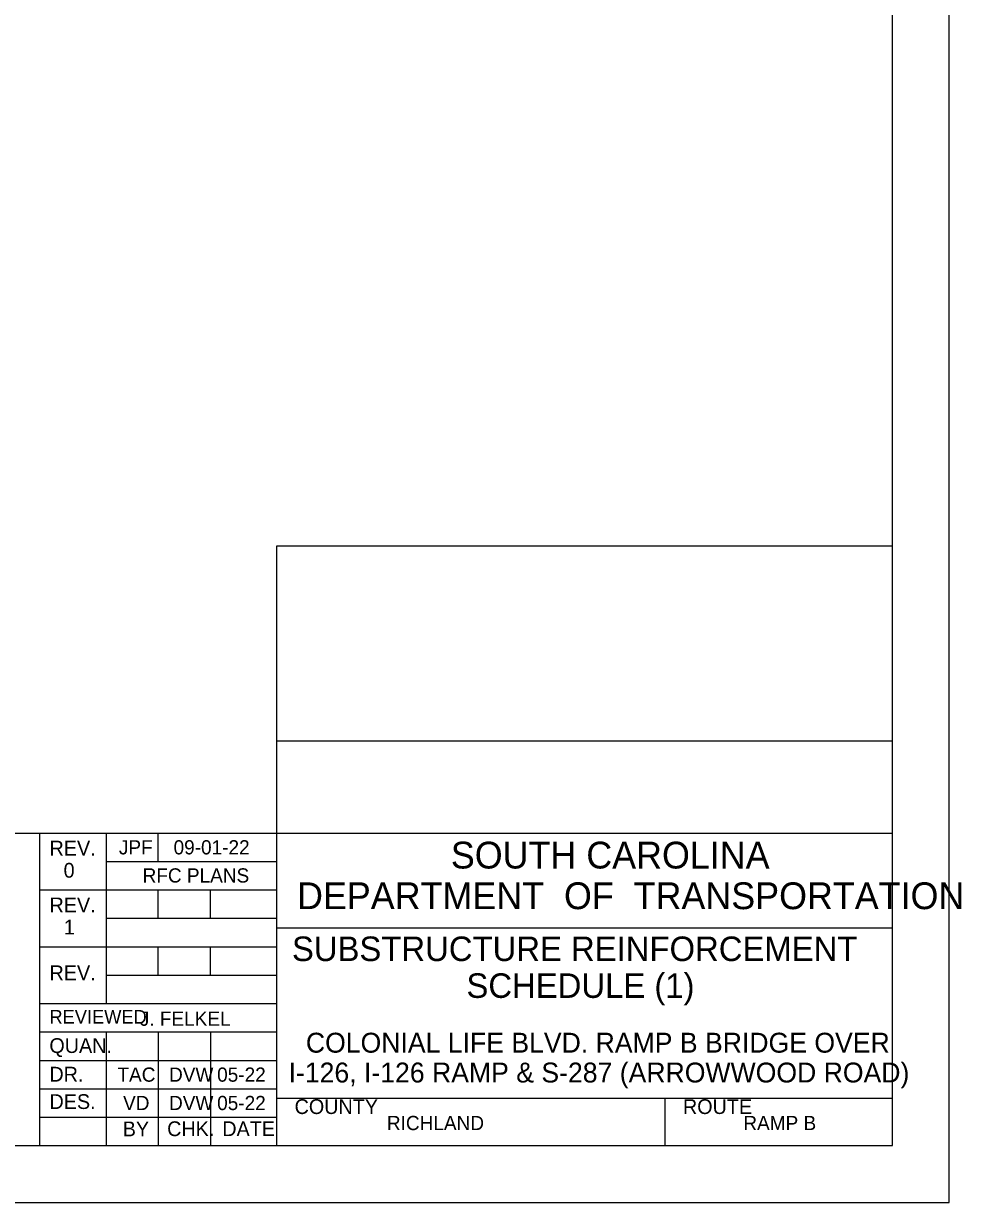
# Model space of a CAD drawing. Extents: x -121.2 to -24.9, y 6.4 to 66.6.
# Drawn here: x -46.88 to -24.88, y 6.35 to 34.01 of the extents above; entities that cross this region are included whole.
import ezdxf

# ---------------------------------------------------------------- set-up
doc = ezdxf.new("R2010")
doc.units = 0
for name, color, linetype in [('BR_BORDER LINES', 7, 'Continuous'), ('BR_TEXT', 7, 'Continuous'), ('Level 31', 7, 'Continuous')]:
    doc.layers.add(name, color=color, linetype=linetype)

msp = doc.modelspace()

# ---------------------------------------------------------------- linework, layer by layer
at = {"layer": 'BR_BORDER LINES'}
for p, q in [((-26.496, 7.683), (-26.496, 63.683)), ((-40.941, 7.683), (-40.941, 21.754)), ((-40.941, 21.754), (-26.496, 21.754)), ((-40.94, 17.182), (-26.496, 17.182)), ((-60.804, 15.017), (-46.496, 15.017)), ((-46.496, 7.683), (-46.496, 15.017)), ((-46.496, 15.017), (-26.496, 15.017)), ((-44.941, 15.017), (-44.941, 11.017)), ((-43.718, 14.35), (-43.718, 15.017)), ((-44.941, 14.35), (-40.941, 14.35)), ((-46.496, 13.684), (-40.941, 13.684)), ((-43.718, 13.017), (-43.718, 13.684)), ((-42.496, 13.017), (-42.496, 13.684)), ((-44.941, 13.017), (-40.941, 13.017)), ((-40.941, 12.795), (-40.941, 12.795)), ((-40.941, 12.795), (-26.495, 12.795)), ((-46.496, 12.35), (-40.941, 12.35)), ((-43.718, 11.684), (-43.718, 12.35)), ((-42.496, 11.684), (-42.496, 12.35)), ((-44.941, 11.684), (-40.941, 11.684)), ((-46.496, 11.017), (-40.941, 11.017)), ((-46.496, 10.35), (-40.941, 10.35)), ((-44.941, 10.35), (-44.941, 7.683)), ((-43.718, 10.35), (-43.718, 7.683)), ((-42.496, 10.35), (-42.496, 7.683)), ((-46.496, 9.683), (-40.941, 9.683)), ((-46.496, 9.017), (-40.941, 9.017)), ((-40.941, 8.795), (-26.496, 8.795)), ((-40.68, 8.795), (-26.496, 8.795)), ((-31.829, 7.683), (-31.829, 8.795)), ((-46.496, 8.35), (-40.941, 8.35)), ((-116.272, 7.683), (-26.496, 7.683))]:
    msp.add_line(p, q, dxfattribs=at)
at = {"layer": 'Level 31'}
msp.add_line((-33.717, 11.621), (-33.717, 11.621), dxfattribs=at)
msp.add_lwpolyline([(-121.161, 6.35), (-25.161, 6.35), (-25.161, 65.017), (-121.161, 65.017)], close=True, dxfattribs=at)

# ---------------------------------------------------------------- texts
at = {"layer": 'BR_TEXT'}
for s, height, p in [('REV.', 0.3467, (-46.27, 14.491)), ('JPF', 0.3333, (-44.643, 14.517)), ('09-01-22', 0.3333, (-43.36, 14.517)), ('SOUTH CAROLINA', 0.62899, (-36.855, 14.186)), ('0', 0.347, (-45.94, 13.971)), ('RFC PLANS', 0.3333, (-44.087, 13.857)), ('DEPARTMENT  OF  TRANSPORTATION', 0.62899, (-40.463, 13.232)), ('REV.', 0.3467, (-46.27, 13.158)), ('1', 0.347, (-45.935, 12.638)), ('SUBSTRUCTURE REINFORCEMENT', 0.576, (-40.583, 12.014)), ('REV.', 0.3467, (-46.27, 11.565)), ('SCHEDULE (1)', 0.576, (-36.489, 11.15)), ('REVIEWED', 0.32, (-46.272, 10.546)), ('J. FELKEL', 0.3333, (-44.152, 10.495)), ('COLONIAL LIFE BLVD. RAMP B BRIDGE OVER', 0.46667, (-40.256, 9.865)), ('QUAN.', 0.3467, (-46.274, 9.857)), ('DR.', 0.3467, (-46.273, 9.186)), ('TAC', 0.3333, (-44.677, 9.183)), ('DVW', 0.3333, (-43.466, 9.183)), ('05-22', 0.3333, (-42.338, 9.183)), ('I-126, I-126 RAMP & S-287 (ARROWWOOD ROAD) ', 0.46667, (-40.662, 9.165)), ('DES.', 0.3467, (-46.271, 8.543)), ('05-22', 0.3333, (-42.338, 8.517)), ('VD', 0.3333, (-44.545, 8.517)), ('DVW', 0.3333, (-43.466, 8.517)), ('COUNTY', 0.3467, (-40.521, 8.425)), ('ROUTE', 0.3467, (-31.41, 8.425)), ('RICHLAND', 0.3333, (-38.355, 8.047)), ('RAMP B', 0.3333, (-29.993, 8.047)), ('BY', 0.3467, (-44.553, 7.902)), ('CHK.', 0.3467, (-43.511, 7.906)), ('DATE', 0.3467, (-42.217, 7.906))]:
    msp.add_text(s, height=height, dxfattribs=at).set_placement(p)

doc.saveas('drawing.dxf')
